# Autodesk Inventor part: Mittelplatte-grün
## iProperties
Created: 2004-10
Part Number: Mittelplatte-grün
Document SubType Name: Modeling
Designer: sahrens
Manufacturer: Standard
Standards Organization: Custom
Author: sahrens
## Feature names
1. Extrusion1
2. Extrusion2
3. Rundung2 [Fillet]
